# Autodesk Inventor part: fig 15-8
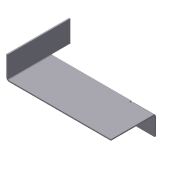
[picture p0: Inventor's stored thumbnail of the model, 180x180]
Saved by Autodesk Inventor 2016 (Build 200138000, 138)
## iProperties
Shininess: 77.0
Angle Display Precision: 2
Document Length Units: 11269
Document Angle Units: 11279
Document Time Units: 11290
Document Mass Units: 11283
Document Length Units Precision: 3
Document Angle Units Precision: 2
Created: 2002-04
Part Number: fig 15-8
Material: Aluminum-6061
Document SubType Name: Sheet Metal
Density: 1 g/cm^3
Sheet Metal Rule: Default
Appearance: Aluminum - Flat-1
Density: 0.0
Volumn: 0.0
Area: 0.0
PropertySet Name: Model Information
Control State: 0
Master: False
Checked Out: False
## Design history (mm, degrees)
node "Face1"
  sketch "Sketch1"
    geometry: L1 (-49.559, 19.574)-(-49.559, -30.426); L2 (-49.559, -30.426)-(50.441, -30.426); L3 (50.441, -30.426)-(50.441, 19.574); L4 (50.441, 19.574)-(32.941, 19.574); L5 (32.941, 19.574)-(32.941, 4.574); L6 (32.941, 4.574)-(-32.059, 4.574); L7 (-32.059, 4.574)-(-32.059, 19.574); L8 (-32.059, 19.574)-(-49.559, 19.574)
    constraints: 16 end point, 6 parallel, 2 equal length, 1 perpendicular, 1 vertical
    dimensions: "d0" = 100 distance of L1.end L2.end; "d1" = 65 distance of L5.end L6.end; "d2" = 15 distance of L6.end L7.end; "d3" = 50 distance of L1.start L1.end
sketch "Sketch2"
  geometry: L1 (100, 0)-(0, 0) reference; L2 (17.5, 50)-(17.5, 35) reference; L3 (82.5, 50)-(82.5, 0)
  constraints: 2 end point, 1 parallel, 1 point on line
sketch "Sketch3"
  geometry: L1 (81.369, -50)-(0, -50) reference; L2 (17.5, 0)-(17.5, -50)
  constraints: 2 end point, 1 perpendicular, 1 point on line
feature "Fold2" sketch "Sketch3" dims "d8" = 1 (= BendRadius), "d9" = 90 deg, "d10" = 1 (= BendRadius), "d14" = 1 (= BendReliefWidth), "d15" = 0.5 (= BendReliefDepth), "d16" = 2 (= MinimumRemnant), "SeamGap" = 0.01, "Thickness" = 1
sketch "Sketch4"
  geometry: L1 (17.5, 0)-(17.5, -50) reference; L2 (-63.869, -15)-(0, -15) reference; L3 (0, -15)-(17.5, -15)
  constraints: 2 end point, 1 collinear, 1 point on line
feature "Fold3" sketch "Sketch4" dims "d11" = 1 (= BendRadius), "d12" = 90 deg, "d13" = 1 (= BendRadius), "d17" = 1 (= BendReliefWidth), "d18" = 0.5 (= BendReliefDepth), "d19" = 2 (= MinimumRemnant), "SeamGap" = 0.01, "Thickness" = 1
body "Solid1"
face "Plate1" dims "Thickness" = 1
other parameters: "BendRadius" = 1 (= Thickness), "BendReliefWidth" = 1 (= Thickness), "BendReliefDepth" = 0.5 (= 0.5 x Thickness), "CornerReliefSize" = 4 (= 4 x Thickness), "MinimumRemnant" = 2 (= 2 x Thickness), "TransitionRadius" = 1 (= BendRadius), "d4" = 1 (= BendRadius), "JacobiRadiusSize" = 1 (= Thickness), "GapSize" = 1 (= Thickness)
